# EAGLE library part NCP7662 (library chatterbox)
Inductorless Voltage Converter
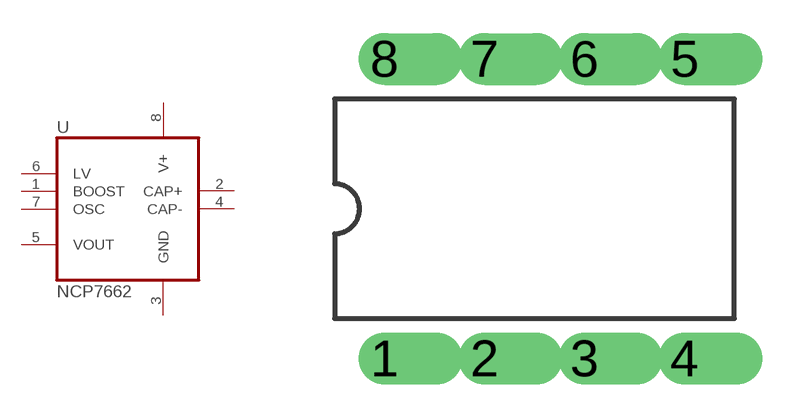
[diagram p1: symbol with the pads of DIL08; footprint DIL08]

Designator prefix -

## NCP7662P  [DIL08]
1  BOOST  in
2  CAP+  pas
3  GND  pwr
4  CAP-  pas
5  VOUT  out
6  LV  pas
7  OSC  in
8  V+  pwr

## Footprint DIL08 (pad centres in mm)
Dual In Line 8
drill 0.813 offset: 1 -3.81,-3.81; 2 -1.27,-3.81; 3 1.27,-3.81; 4 3.81,-3.81; 5 3.81,3.81; 6 1.27,3.81; 7 -1.27,3.81; 8 -3.81,3.81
